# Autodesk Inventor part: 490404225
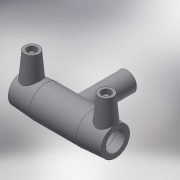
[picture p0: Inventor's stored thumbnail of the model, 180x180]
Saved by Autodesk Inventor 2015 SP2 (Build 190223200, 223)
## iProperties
Created: 2017-06
Part Number: 490404225
Material: Generic
Description: PLASSON TEE 225-225-225
Document SubType Name: Modeling
Designer: KIM
Mass: 57.3761 g
Surface Area: 241.06 cm^2
Volume: 57.3761 cm^3
Density: 1 g/cm^3
Appearance: Default
Author: KIM
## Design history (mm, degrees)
derived "490404.ipt"
feature "Solid1::490404.ipt"
tag "TaggingFeature1"
body "Solid1"
other parameters: "d0" = 494, "d1" = 225, "d2" = 293, "d3" = 122, "d4" = 123.5, "d5" = 263.7, "d6" = 213.75, "d7" = 225, "d8" = 168 deg, "d10" = 48.8, "d11" = 16.26667, "d13" = 494, "d14" = 17.6296, "d17" = 202.5, "d18" = 225, "d19" = 3.52592, "d20" = 168 deg, "d22" = 272.49, "d23" = 293, "d24" = 264.3153, "d25" = 135 deg, "d26" = 345.8, "d27" = 135 deg, "d30" = 15, "d31" = 197.6, "d34" = 5 deg, "d35" = 15, "d39" = 5 deg, "d40" = 9.6, "d41" = 4.8, "d42" = 6, "d43" = 0, "d45" = 4, "d46" = 14, "d47" = 0, "d49" = 225, "d51" = 0, "d54" = 0, "d55" = 263.7, "d56" = 293, "d57" = 172.9, "d58" = 135 deg, "d59" = 122, "d60" = 122, "d61" = 135 deg, "d72" = 242.06, "d73" = 121.03, "d75" = 236.25, "d77" = 0, "d80" = 0, "d81" = 225, "d82" = 143.5, "d83" = 0, "d84" = 3, "d85" = 0, "d86" = 3, "d87" = 0, "d88" = 35.38, "d89" = 8.845, "d90" = 35.38, "d_" = 225, "L_" = 494, "L_1" = 122, "D_" = 293, "d_2" = 12
